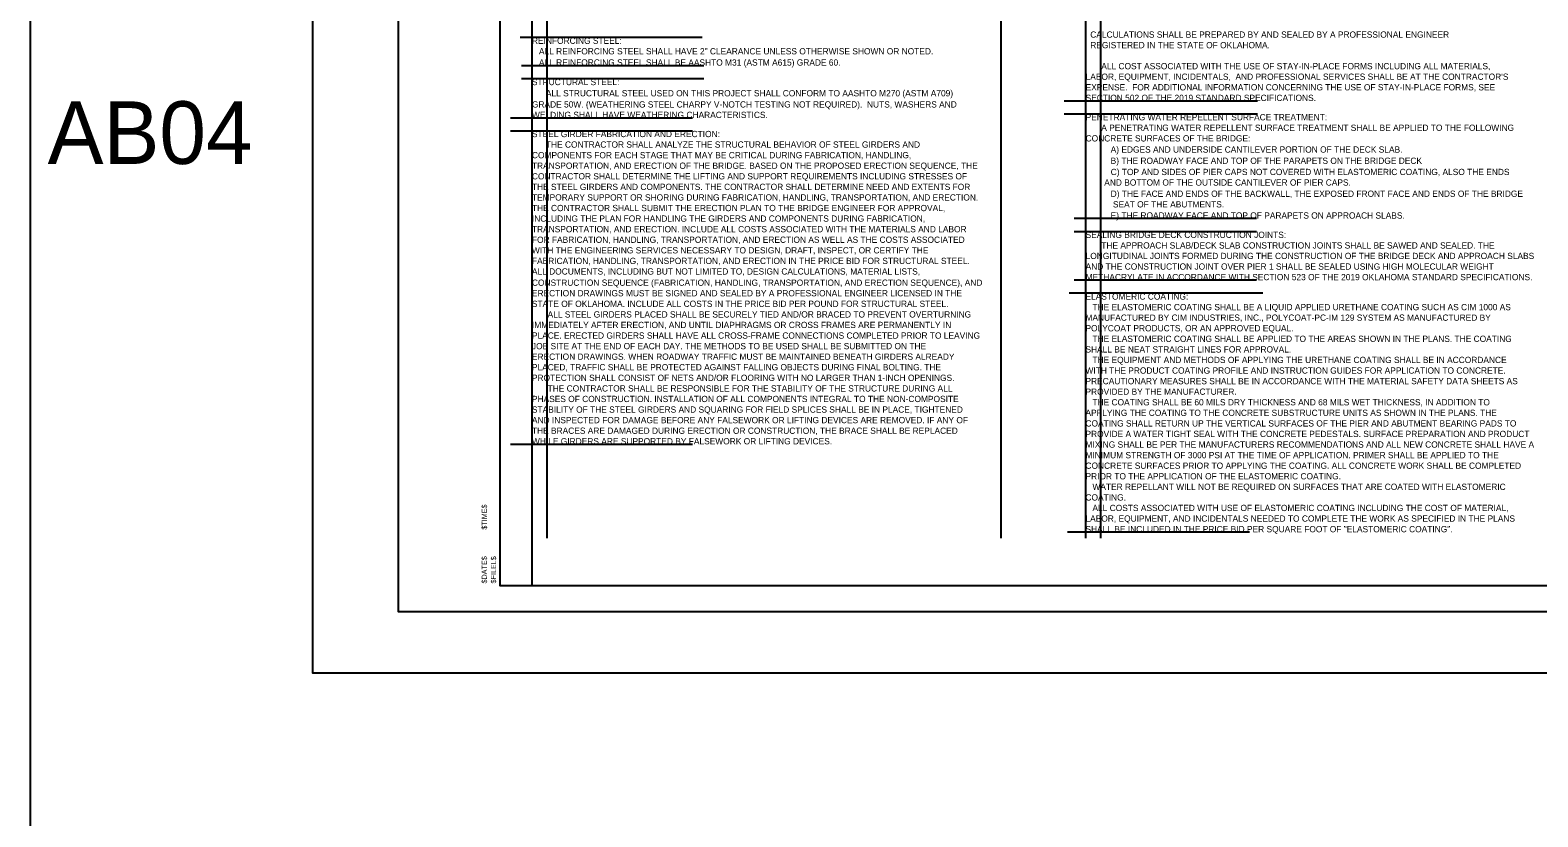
# Model space of a CAD drawing. Extents: x 12310.9 to 12354.4, y 579 to 640.5.
# Drawn here: x 12310.94 to 12339.83, y 610.44 to 625.51 of the extents above; entities that cross this region are included whole.
import ezdxf

# ---------------------------------------------------------------- set-up
doc = ezdxf.new("R2010")
doc.units = 0
for name, color, linetype in [('S', 7, 'Continuous'), ('SHT_Plot_Shape_Full', 7, 'Continuous'), ('SHT_Plot_Shape_Half', 7, 'Continuous'), ('SHT_Plot_Stamp', 7, 'Continuous'), ('SHT_Sheet_Border', 7, 'Continuous'), ('T', 7, 'Continuous')]:
    doc.layers.add(name, color=color, linetype=linetype)

# ---------------------------------------------------------------- blocks, each defined once
blk = doc.blocks.new('Stamp_Plot_Stamp')
at = {"layer": 'SHT_Plot_Stamp'}
for s, p in [('$TIME$', (8.01, 7.43)), ('$DATE$', (8.01, 2.56)), ('$FILEL$', (8.85, 2.56))]:
    blk.add_text(s, height=0.472, rotation=90, dxfattribs=at).set_placement(p)

msp = doc.modelspace()

# ---------------------------------------------------------------- linework, layer by layer
at = {"layer": 'Defpoints'}
for p, q in [((12320.557, 635.43), (12320.557, 614.872)), ((12320.841, 635.43), (12320.841, 615.78)), ((12329.542, 635.43), (12329.542, 615.78)), ((12331.165, 635.43), (12331.165, 615.78)), ((12331.45, 635.43), (12331.45, 615.78)), ((12323.819, 625.372), (12320.33, 625.372)), ((12323.848, 624.834), (12320.358, 624.834)), ((12323.848, 624.584), (12320.358, 624.584)), ((12334.242, 624.157), (12330.752, 624.157)), ((12334.458, 624.157), (12330.969, 624.157)), ((12323.633, 623.831), (12320.144, 623.831)), ((12334.242, 623.907), (12330.752, 623.907)), ((12334.458, 623.907), (12330.969, 623.907)), ((12323.633, 623.581), (12320.144, 623.581)), ((12334.436, 621.904), (12330.946, 621.904)), ((12334.436, 621.654), (12330.946, 621.654)), ((12334.34, 620.474), (12330.85, 620.474)), ((12334.436, 620.724), (12330.946, 620.724)), ((12334.436, 620.474), (12330.946, 620.474)), ((12334.562, 620.474), (12331.072, 620.474)), ((12323.633, 617.579), (12320.144, 617.579)), ((12334.307, 615.895), (12330.817, 615.895))]:
    msp.add_line(p, q, dxfattribs=at)
at = {"layer": 'S'}
msp.add_lwpolyline([(12354.38, 640.488), (12310.944, 640.488), (12310.944, 579.031), (12354.38, 579.031)], close=True, dxfattribs=at)
at = {"layer": 'SHT_Plot_Shape_Full'}
msp.add_lwpolyline([(12316.36, 637.197), (12352.36, 637.197), (12352.36, 613.197), (12316.36, 613.197)], close=True, dxfattribs=at)
at = {"layer": 'SHT_Plot_Shape_Half'}
msp.add_lwpolyline([(12317.998, 636.372), (12351.998, 636.372), (12351.998, 614.372), (12317.998, 614.372)], close=True, dxfattribs=at)
at = {"layer": 'SHT_Sheet_Border'}
msp.add_lwpolyline([(12351.448, 614.872), (12319.948, 614.872), (12319.948, 635.872), (12351.448, 635.872)], close=True, dxfattribs=at)

# ---------------------------------------------------------------- block references
at = {"layer": 'SHT_Plot_Stamp', "xscale": 0.21166666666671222, "yscale": 0.21166666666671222}
msp.add_blockref('Stamp_Plot_Stamp', (12317.998, 614.372), dxfattribs=at)

# ---------------------------------------------------------------- texts
at = {"layer": 'T'}
for s, height, p in [('REINFORCING STEEL:', 0.12, (12320.557, 625.252)), ('  CALCULATIONS SHALL BE PREPARED BY AND SEALED BY A PROFESSIONAL ENGINEER', 0.12, (12331.165, 625.37)), ('   ALL REINFORCING STEEL SHALL HAVE 2" CLEARANCE UNLESS OTHERWISE SHOWN OR NOTED.', 0.12, (12320.557, 625.05)), ('  REGISTERED IN THE STATE OF OKLAHOMA.', 0.12, (12331.165, 625.168)), ('   ALL REINFORCING STEEL SHALL BE AASHTO M31 (ASTM A615) GRADE 60.', 0.12, (12320.557, 624.835)), ('ALL COST ASSOCIATED WITH THE USE OF STAY-IN-PLACE FORMS INCLUDING ALL MATERIALS, ', 0.12, (12331.465, 624.765)), ('STRUCTURAL STEEL:', 0.12, (12320.557, 624.461)), ("LABOR, EQUIPMENT, INCIDENTALS,  AND PROFESSIONAL SERVICES SHALL BE AT THE CONTRACTOR'S ", 0.12, (12331.165, 624.563)), ('      ALL STRUCTURAL STEEL USED ON THIS PROJECT SHALL CONFORM TO AASHTO M270 (ASTM A709) ', 0.12, (12320.557, 624.246)), ('SECTION 502 OF THE 2019 STANDARD SPECIFICATIONS.', 0.12, (12331.165, 624.157)), ('EXPENSE.  FOR ADDITIONAL INFORMATION CONCERNING THE USE OF STAY-IN-PLACE FORMS, SEE ', 0.12, (12331.165, 624.36)), ('AB04', 1.2, (12311.279, 622.951)), ('WELDING SHALL HAVE WEATHERING CHARACTERISTICS.', 0.12, (12320.557, 623.831)), ('GRADE 50W. (WEATHERING STEEL CHARPY V-NOTCH TESTING NOT REQUIRED).  NUTS, WASHERS AND ', 0.12, (12320.557, 624.032)), ('PENETRATING WATER REPELLENT SURFACE TREATMENT:', 0.12, (12331.165, 623.787)), ('A PENETRATING WATER REPELLENT SURFACE TREATMENT SHALL BE APPLIED TO THE FOLLOWING ', 0.12, (12331.465, 623.585)), ('STEEL GIRDER FABRICATION AND ERECTION:', 0.12, (12320.557, 623.465)), ('      THE CONTRACTOR SHALL ANALYZE THE STRUCTURAL BEHAVIOR OF STEEL GIRDERS AND ', 0.12, (12320.557, 623.263)), ('CONCRETE SURFACES OF THE BRIDGE:', 0.12, (12331.165, 623.382)), ('COMPONENTS FOR EACH STAGE THAT MAY BE CRITICAL DURING FABRICATION, HANDLING, ', 0.12, (12320.557, 623.06)), ('A) EDGES AND UNDERSIDE CANTILEVER PORTION OF THE DECK SLAB.', 0.12, (12331.645, 623.168)), ('B) THE ROADWAY FACE AND TOP OF THE PARAPETS ON THE BRIDGE DECK', 0.12, (12331.645, 622.953)), ('TRANSPORTATION, AND ERECTION OF THE BRIDGE. BASED ON THE PROPOSED ERECTION SEQUENCE, THE ', 0.12, (12320.557, 622.858)), ('CONTRACTOR SHALL DETERMINE THE LIFTING AND SUPPORT REQUIREMENTS INCLUDING STRESSES OF ', 0.12, (12320.557, 622.655)), ('C) TOP AND SIDES OF PIER CAPS NOT COVERED WITH ELASTOMERIC COATING, ALSO THE ENDS ', 0.12, (12331.645, 622.738)), ('THE STEEL GIRDERS AND COMPONENTS. THE CONTRACTOR SHALL DETERMINE NEED AND EXTENTS FOR ', 0.12, (12320.557, 622.452)), ('        AND BOTTOM OF THE OUTSIDE CANTILEVER OF PIER CAPS.', 0.12, (12331.165, 622.536)), ('TEMPORARY SUPPORT OR SHORING DURING FABRICATION, HANDLING, TRANSPORTATION, AND ERECTION. ', 0.12, (12320.557, 622.25)), ('D) THE FACE AND ENDS OF THE BACKWALL, THE EXPOSED FRONT FACE AND ENDS OF THE BRIDGE    ', 0.12, (12331.645, 622.321)), ('     SEAT OF THE ABUTMENTS.', 0.12, (12331.465, 622.118)), ('THE CONTRACTOR SHALL SUBMIT THE ERECTION PLAN TO THE BRIDGE ENGINEER FOR APPROVAL, ', 0.12, (12320.557, 622.047)), ('INCLUDING THE PLAN FOR HANDLING THE GIRDERS AND COMPONENTS DURING FABRICATION, ', 0.12, (12320.557, 621.845)), ('E) THE ROADWAY FACE AND TOP OF PARAPETS ON APPROACH SLABS.', 0.12, (12331.645, 621.904)), ('TRANSPORTATION, AND ERECTION. INCLUDE ALL COSTS ASSOCIATED WITH THE MATERIALS AND LABOR ', 0.12, (12320.557, 621.642)), ('SEALING BRIDGE DECK CONSTRUCTION JOINTS:', 0.12, (12331.165, 621.534)), ('WITH THE ENGINEERING SERVICES NECESSARY TO DESIGN, DRAFT, INSPECT, OR CERTIFY THE ', 0.12, (12320.557, 621.237)), ('FOR FABRICATION, HANDLING, TRANSPORTATION, AND ERECTION AS WELL AS THE COSTS ASSOCIATED ', 0.12, (12320.557, 621.44)), ('THE APPROACH SLAB/DECK SLAB CONSTRUCTION JOINTS SHALL BE SAWED AND SEALED. THE ', 0.12, (12331.465, 621.331)), ('FABRICATION, HANDLING, TRANSPORTATION, AND ERECTION IN THE PRICE BID FOR STRUCTURAL STEEL. ', 0.12, (12320.557, 621.034)), ('AND THE CONSTRUCTION JOINT OVER PIER 1 SHALL BE SEALED USING HIGH MOLECULAR WEIGHT ', 0.12, (12331.165, 620.926)), ('LONGITUDINAL JOINTS FORMED DURING THE CONSTRUCTION OF THE BRIDGE DECK AND APPROACH SLABS ', 0.12, (12331.165, 621.129)), ('ALL DOCUMENTS, INCLUDING BUT NOT LIMITED TO, DESIGN CALCULATIONS, MATERIAL LISTS, ', 0.12, (12320.557, 620.832)), ('CONSTRUCTION SEQUENCE (FABRICATION, HANDLING, TRANSPORTATION, AND ERECTION SEQUENCE), AND ', 0.12, (12320.557, 620.617)), ('METHACRYLATE IN ACCORDANCE WITH SECTION 523 OF THE 2019 OKLAHOMA STANDARD SPECIFICATIONS.', 0.12, (12331.165, 620.724)), ('ERECTION DRAWINGS MUST BE SIGNED AND SEALED BY A PROFESSIONAL ENGINEER LICENSED IN THE ', 0.12, (12320.557, 620.415)), ('ELASTOMERIC COATING:', 0.12, (12331.162, 620.352)), ('STATE OF OKLAHOMA. INCLUDE ALL COSTS IN THE PRICE BID PER POUND FOR STRUCTURAL STEEL.', 0.12, (12320.557, 620.212)), ('   THE ELASTOMERIC COATING SHALL BE A LIQUID APPLIED URETHANE COATING SUCH AS CIM 1000 AS ', 0.12, (12331.162, 620.149)), ('IMMEDIATELY AFTER ERECTION, AND UNTIL DIAPHRAGMS OR CROSS FRAMES ARE PERMANENTLY IN ', 0.12, (12320.557, 619.807)), ('ALL STEEL GIRDERS PLACED SHALL BE SECURELY TIED AND/OR BRACED TO PREVENT OVERTURNING ', 0.12, (12320.857, 620.009)), ('MANUFACTURED BY CIM INDUSTRIES, INC., POLYCOAT-PC-IM 129 SYSTEM AS MANUFACTURED BY ', 0.12, (12331.162, 619.947)), ('PLACE. ERECTED GIRDERS SHALL HAVE ALL CROSS-FRAME CONNECTIONS COMPLETED PRIOR TO LEAVING ', 0.12, (12320.557, 619.604)), ('POLYCOAT PRODUCTS, OR AN APPROVED EQUAL.', 0.12, (12331.162, 619.744)), ('   THE ELASTOMERIC COATING SHALL BE APPLIED TO THE AREAS SHOWN IN THE PLANS. THE COATING ', 0.12, (12331.162, 619.542)), ('JOB SITE AT THE END OF EACH DAY. THE METHODS TO BE USED SHALL BE SUBMITTED ON THE ', 0.12, (12320.557, 619.402)), ('ERECTION DRAWINGS. WHEN ROADWAY TRAFFIC MUST BE MAINTAINED BENEATH GIRDERS ALREADY ', 0.12, (12320.557, 619.199)), ('SHALL BE NEAT STRAIGHT LINES FOR APPROVAL.', 0.12, (12331.162, 619.339)), ('PLACED, TRAFFIC SHALL BE PROTECTED AGAINST FALLING OBJECTS DURING FINAL BOLTING. THE ', 0.12, (12320.557, 618.997)), ('WITH THE PRODUCT COATING PROFILE AND INSTRUCTION GUIDES FOR APPLICATION TO CONCRETE. ', 0.12, (12331.162, 618.934)), ('   THE EQUIPMENT AND METHODS OF APPLYING THE URETHANE COATING SHALL BE IN ACCORDANCE ', 0.12, (12331.162, 619.137)), ('PROTECTION SHALL CONSIST OF NETS AND/OR FLOORING WITH NO LARGER THAN 1-INCH OPENINGS. ', 0.12, (12320.557, 618.794)), ('PRECAUTIONARY MEASURES SHALL BE IN ACCORDANCE WITH THE MATERIAL SAFETY DATA SHEETS AS ', 0.12, (12331.162, 618.731)), ('PHASES OF CONSTRUCTION. INSTALLATION OF ALL COMPONENTS INTEGRAL TO THE NON-COMPOSITE ', 0.12, (12320.557, 618.389)), ('THE CONTRACTOR SHALL BE RESPONSIBLE FOR THE STABILITY OF THE STRUCTURE DURING ALL ', 0.12, (12320.857, 618.591)), ('PROVIDED BY THE MANUFACTURER.', 0.12, (12331.162, 618.529)), ('   THE COATING SHALL BE 60 MILS DRY THICKNESS AND 68 MILS WET THICKNESS, IN ADDITION TO ', 0.12, (12331.162, 618.326)), ('STABILITY OF THE STEEL GIRDERS AND SQUARING FOR FIELD SPLICES SHALL BE IN PLACE, TIGHTENED ', 0.12, (12320.557, 618.186)), ('APPLYING THE COATING TO THE CONCRETE SUBSTRUCTURE UNITS AS SHOWN IN THE PLANS. THE ', 0.12, (12331.162, 618.124)), ('AND INSPECTED FOR DAMAGE BEFORE ANY FALSEWORK OR LIFTING DEVICES ARE REMOVED. IF ANY OF ', 0.12, (12320.557, 617.984)), ('THE BRACES ARE DAMAGED DURING ERECTION OR CONSTRUCTION, THE BRACE SHALL BE REPLACED ', 0.12, (12320.557, 617.781)), ('COATING SHALL RETURN UP THE VERTICAL SURFACES OF THE PIER AND ABUTMENT BEARING PADS TO ', 0.12, (12331.162, 617.921)), ('WHILE GIRDERS ARE SUPPORTED BY FALSEWORK OR LIFTING DEVICES.', 0.12, (12320.557, 617.579)), ('PROVIDE A WATER TIGHT SEAL WITH THE CONCRETE PEDESTALS. SURFACE PREPARATION AND PRODUCT ', 0.12, (12331.162, 617.719)), ('MIXING SHALL BE PER THE MANUFACTURERS RECOMMENDATIONS AND ALL NEW CONCRETE SHALL HAVE A ', 0.12, (12331.162, 617.516)), ('MINIMUM STRENGTH OF 3000 PSI AT THE TIME OF APPLICATION. PRIMER SHALL BE APPLIED TO THE ', 0.12, (12331.162, 617.313)), ('CONCRETE SURFACES PRIOR TO APPLYING THE COATING. ALL CONCRETE WORK SHALL BE COMPLETED ', 0.12, (12331.162, 617.111)), ('PRIOR TO THE APPLICATION OF THE ELASTOMERIC COATING.', 0.12, (12331.162, 616.908)), ('   WATER REPELLANT WILL NOT BE REQUIRED ON SURFACES THAT ARE COATED WITH ELASTOMERIC ', 0.12, (12331.162, 616.706)), ('COATING.', 0.12, (12331.162, 616.503)), ('   ALL COSTS ASSOCIATED WITH USE OF ELASTOMERIC COATING INCLUDING THE COST OF MATERIAL, ', 0.12, (12331.162, 616.301)), ('LABOR, EQUIPMENT, AND INCIDENTALS NEEDED TO COMPLETE THE WORK AS SPECIFIED IN THE PLANS ', 0.12, (12331.162, 616.098)), ('SHALL BE INCLUDED IN THE PRICE BID PER SQUARE FOOT OF "ELASTOMERIC COATING".', 0.12, (12331.162, 615.895))]:
    msp.add_text(s, height=height, dxfattribs=at).set_placement(p)

doc.saveas('drawing.dxf')
